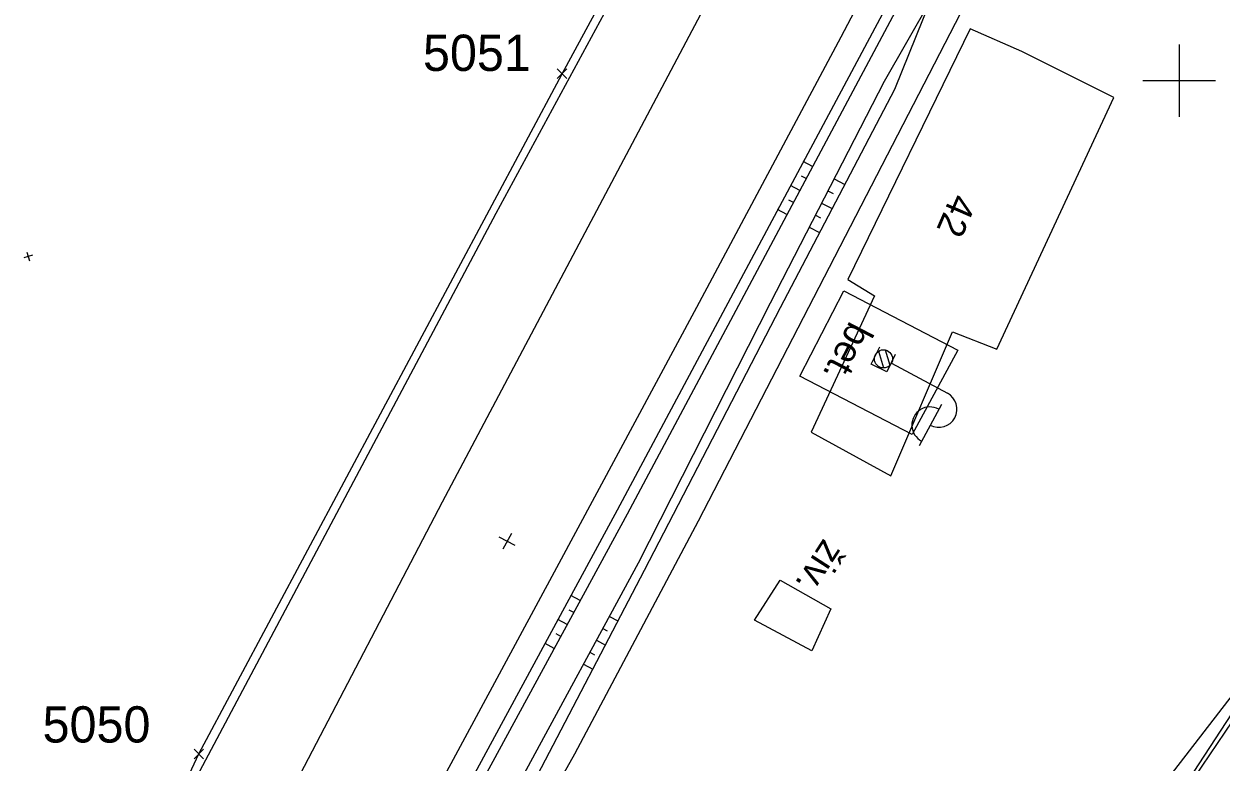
# Model space of a CAD drawing. Extents: x -795094 to -794639, y -1135368 to -1134681.
# Drawn here: x -794863.7 to -794797.7, y -1134937.6 to -1134896.9 of the extents above; entities that cross this region are included whole.
import ezdxf

# ---------------------------------------------------------------- set-up
doc = ezdxf.new("R2010")
doc.units = 0
for name, color, linetype in [('0381KM005-009P - Vrstva 1', 7, 'Continuous'), ('0381KM005-009P - Vrstva 16', 7, 'Continuous'), ('0381KM005-009P - Vrstva 17', 7, 'Continuous'), ('0381KM005-009P - Vrstva 23', 7, 'Continuous'), ('0381KM005-009P - Vrstva 25', 7, 'Continuous'), ('0381KM005-009P - Vrstva 48', 7, 'Continuous'), ('0381KM005-009P - Vrstva 49', 7, 'Continuous'), ('0381KM005-009P - Vrstva 55', 7, 'Continuous'), ('0381KM005-009P - Vrstva 57', 7, 'Continuous'), ('0381KM005-009P - Vrstva 7', 7, 'Continuous'), ('krizky_1000 - Vrstva 1', 7, 'Continuous'), ('szdc - hran DP', 7, 'Continuous'), ('szdc - szdc_cislo', 7, 'Continuous'), ('szdc - szdc_krizek', 7, 'Continuous')]:
    doc.layers.add(name, color=color, linetype=linetype)

msp = doc.modelspace()

# ---------------------------------------------------------------- linework, layer by layer
at = {"layer": '0381KM005-009P - Vrstva 1'}
for points in [[(-794788.584, -1134840.279), (-794803.188, -1134868.16), (-794810.376, -1134881.864), (-794818.661, -1134897.596), (-794826.62, -1134912.502), (-794834.335, -1134926.852), (-794861.916, -1134977.994)], [(-794786.958, -1134841.365), (-794793.838, -1134858.325), (-794800.908, -1134874.123), (-794807.726, -1134887.87), (-794826.516, -1134924.295), (-794833.336, -1134937.128), (-794839.366, -1134947.862), (-794840.749, -1134950.163), (-794846.082, -1134958.608), (-794850.879, -1134965.553), (-794860.098, -1134978.738)]]:
    msp.add_lwpolyline(points, dxfattribs=at)
at = {"layer": '0381KM005-009P - Vrstva 16'}
for points in [[(-794818.484, -1134911.585), (-794812.195, -1134914.869), (-794814.713, -1134919.505), (-794820.925, -1134916.287), (-794818.484, -1134911.585)], [(-794821.999, -1134927.542), (-794819.206, -1134929.128), (-794820.252, -1134931.433), (-794823.424, -1134929.746), (-794821.999, -1134927.542)]]:
    msp.add_lwpolyline(points, dxfattribs=at)
at = {"layer": '0381KM005-009P - Vrstva 17'}
msp.add_lwpolyline([(-794815.659, -1134915.106), (-794816.112, -1134916.052), (-794816.987, -1134915.632), (-794816.503, -1134914.671)], dxfattribs=at)
at = {"layer": '0381KM005-009P - Vrstva 25'}
for p, q in [((-794816.575, -1134914.923), (-794816.299, -1134915.839)), ((-794816.205, -1134914.85), (-794815.952, -1134915.692)), ((-794815.863, -1134915.577), (-794812.78, -1134917.234)), ((-794813.111, -1134917.851), (-794814.343, -1134920.141))]:
    msp.add_line(p, q, dxfattribs=at)
msp.add_circle((-794816.303, -1134915.34), 0.5, dxfattribs=at)
for centre, start, end in [((-794813.253, -1134918.115), 241.73616, 61.73616), ((-794813.738, -1134918.99), 61.03359, 242.43873)]:
    msp.add_arc(centre, 1, start, end, dxfattribs=at)
at = {"layer": '0381KM005-009P - Vrstva 48'}
for p, q in [((-794820.214, -1134904.734), (-794820.726, -1134904.461)), ((-794820.567, -1134905.396), (-794820.823, -1134905.259)), ((-794820.92, -1134906.058), (-794821.433, -1134905.784)), ((-794819.027, -1134905.414), (-794818.436, -1134905.717)), ((-794821.273, -1134906.719), (-794821.53, -1134906.582)), ((-794819.37, -1134906.081), (-794819.077, -1134906.231)), ((-794821.626, -1134907.381), (-794822.14, -1134907.107)), ((-794819.713, -1134906.748), (-794819.132, -1134907.046)), ((-794820.056, -1134907.415), (-794819.768, -1134907.562)), ((-794820.399, -1134908.082), (-794819.829, -1134908.375)), ((-794833.029, -1134928.666), (-794833.541, -1134928.388)), ((-794833.745, -1134929.984), (-794834.255, -1134929.707)), ((-794833.387, -1134929.325), (-794833.642, -1134929.186)), ((-794831.418, -1134929.538), (-794830.947, -1134929.792)), ((-794831.775, -1134930.197), (-794831.535, -1134930.327)), ((-794834.461, -1134931.302), (-794834.969, -1134931.026)), ((-794834.103, -1134930.643), (-794834.357, -1134930.505)), ((-794832.132, -1134930.857), (-794831.642, -1134931.122)), ((-794832.488, -1134931.516), (-794832.239, -1134931.651)), ((-794832.845, -1134932.176), (-794832.338, -1134932.451))]:
    msp.add_line(p, q, dxfattribs=at)
at = {"layer": '0381KM005-009P - Vrstva 49'}
for p, q in [((-794799.26, -1134845.148), (-794840.647, -1134923.239)), ((-794824.731, -1134883.385), (-794837.684, -1134907.328)), ((-794837.684, -1134907.328), (-794854.176, -1134938.373)), ((-794863.226, -1134909.628), (-794863.704, -1134909.772)), ((-794863.537, -1134909.461), (-794863.393, -1134909.939)), ((-794840.647, -1134923.239), (-794855.687, -1134952.034)), ((-794792.988, -1134928.575), (-794819.559, -1134969.298)), ((-794792.988, -1134928.575), (-794819.082, -1134962.417))]:
    msp.add_line(p, q, dxfattribs=at)
for points in [[(-794815.371, -1134894.435), (-794815.665, -1134896.209), (-794830.438, -1134923.896), (-794846.524, -1134953.505), (-794848.275, -1134955.609)], [(-794815.371, -1134894.435), (-794830.99, -1134923.676), (-794848.275, -1134955.609)], [(-794813.726, -1134895.612), (-794815.698, -1134900.493), (-794822.002, -1134912.521), (-794829.492, -1134927.011), (-794835.621, -1134938.728), (-794838.097, -1134942.656)], [(-794813.726, -1134895.612), (-794816.272, -1134900.056), (-794822.552, -1134912.269), (-794829.828, -1134926.6), (-794836.239, -1134938.447), (-794838.097, -1134942.656)]]:
    msp.add_lwpolyline(points, dxfattribs=at)
at = {"layer": '0381KM005-009P - Vrstva 55'}
msp.add_lwpolyline([(-794815.9, -1134921.79), (-794812.5, -1134913.85), (-794810.05, -1134914.8), (-794803.6, -1134900.93), (-794808.67, -1134898.39), (-794811.52, -1134897.15), (-794818.27, -1134910.96), (-794816.8, -1134911.86), (-794820.3, -1134919.39), (-794815.9, -1134921.79)], dxfattribs=at)
at = {"layer": '0381KM005-009P - Vrstva 7'}
for p, q in [((-794836.812, -1134924.959), (-794837.286, -1134925.839)), ((-794836.609, -1134925.636), (-794837.489, -1134925.162))]:
    msp.add_line(p, q, dxfattribs=at)
at = {"layer": 'krizky_1000 - Vrstva 1'}
for points in [[(-794800, -1134898), (-794800, -1134902)], [(-794802, -1134900), (-794798, -1134900)]]:
    msp.add_lwpolyline(points, dxfattribs=at)
at = {"layer": 'szdc - hran DP'}
for p, q in [((-794834.03, -1134899.62), (-794808.02, -1134851.51)), ((-794771.93, -1134898.11), (-794808.62, -1134952.39)), ((-794854.06, -1134937.12), (-794834.03, -1134899.62)), ((-794861.46, -1134953), (-794854.06, -1134937.12))]:
    msp.add_line(p, q, dxfattribs=at)
at = {"layer": 'szdc - szdc_krizek'}
for p, q in [((-794833.765, -1134899.885), (-794834.296, -1134899.355)), ((-794834.296, -1134899.885), (-794833.765, -1134899.355)), ((-794853.795, -1134937.385), (-794854.326, -1134936.855)), ((-794854.326, -1134937.385), (-794853.795, -1134936.855))]:
    msp.add_line(p, q, dxfattribs=at)

# ---------------------------------------------------------------- texts
at = {"layer": '0381KM005-009P - Vrstva 16'}
for s, rotation, p in [('bet.', 242.56433, (-794818.151, -1134913.196)), ('živ.', 237.11524, (-794819.598, -1134925.193))]:
    msp.add_text(s, height=1.5, rotation=rotation, dxfattribs=at).set_placement(p)
at = {"layer": '0381KM005-009P - Vrstva 23'}
msp.add_text('žst. Strunkovice nad Volyňkou', height=8, rotation=245.66299, dxfattribs=at).set_placement((-794771.538, -1134921.216))
at = {"layer": '0381KM005-009P - Vrstva 57'}
msp.add_text('42', height=1.5, rotation=246.65864, dxfattribs=at).set_placement((-794812.519, -1134906.143))
at = {"layer": 'szdc - szdc_cislo'}
for s, p in [('5051', (-794841.699, -1134899.465)), ('5050', (-794862.677, -1134936.493))]:
    msp.add_text(s, height=2, dxfattribs=at).set_placement(p)

doc.saveas('drawing.dxf')
